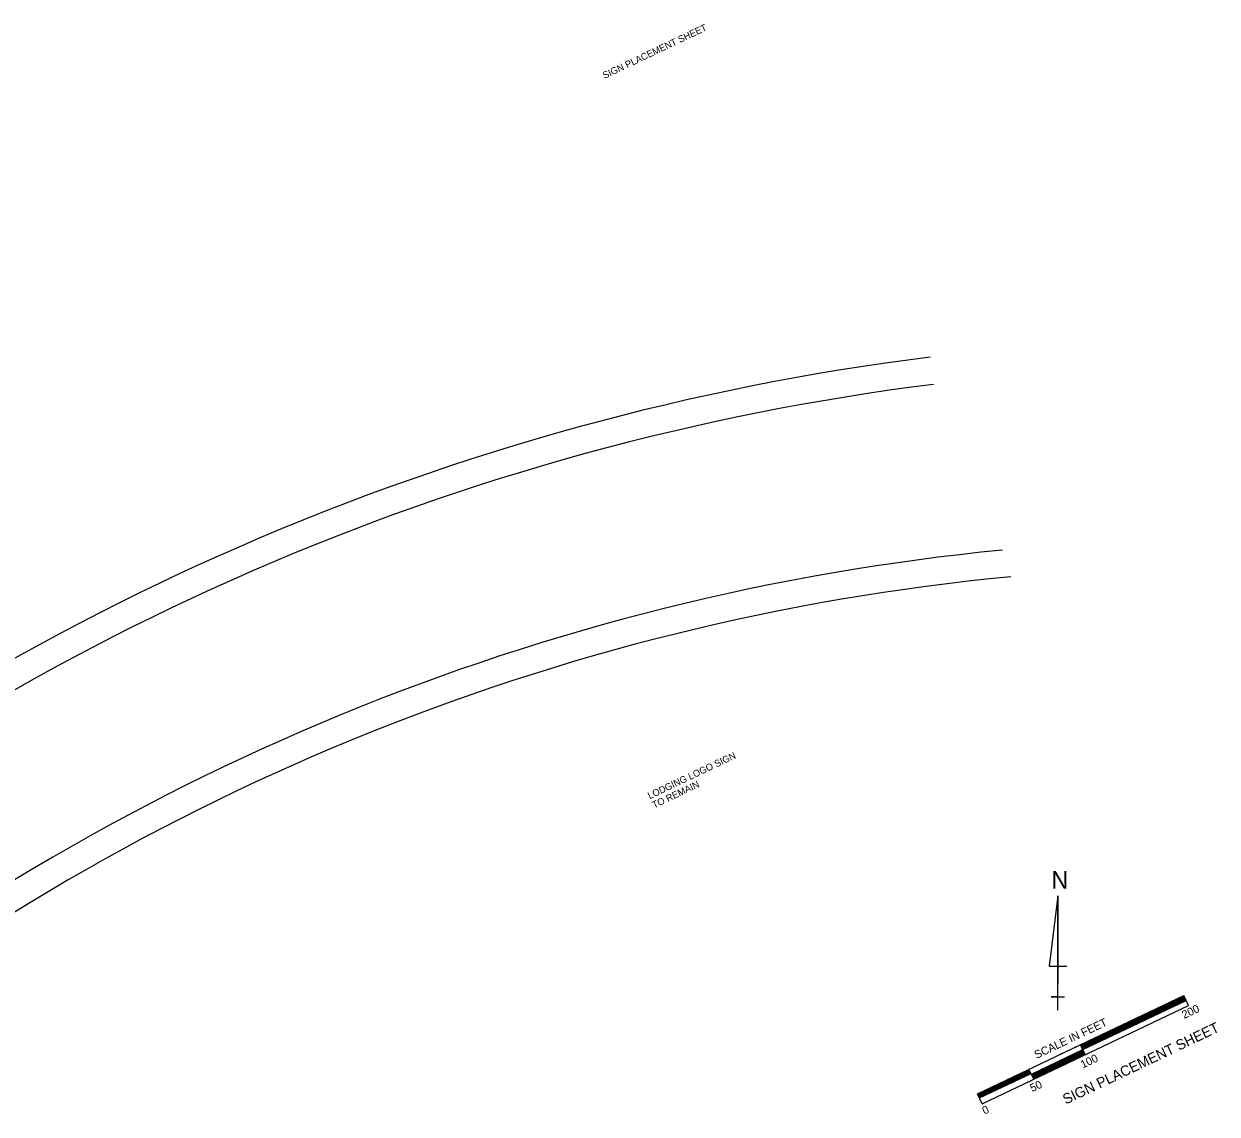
# Model space of a CAD drawing. Extents: x 601881 to 611898, y 415511 to 421131.
# Drawn here: x 602925 to 603969, y 420177 to 421131 of the extents above; entities that cross this region are included whole.
import ezdxf

# ---------------------------------------------------------------- set-up
doc = ezdxf.new("R2010")
doc.units = 0
for name, color, linetype in [('G-ANNO-TEXT', 7, 'Continuous'), ('Level 1', 7, 'Continuous'), ('Level 10', 7, 'Continuous'), ('R_Annotation', 7, 'Continuous'), ('R_Draft', 7, 'Continuous')]:
    doc.layers.add(name, color=color, linetype=linetype)

msp = doc.modelspace()

# ---------------------------------------------------------------- linework, layer by layer
at = {"layer": 'Level 1'}
for p, q in [((603829.6, 420367.5), (603821.9, 420306)), ((603829.6, 420267.5), (603829.6, 420367.5)), ((603829.6, 420367.5), (603829.6, 420290.6)), ((603821.9, 420306), (603837.3, 420306)), ((603829.6, 420267.5), (603829.6, 420290.6)), ((603829.6, 420279.1), (603823.8, 420279.1)), ((603823.8, 420279.1), (603835.3, 420279.1)), ((603829.6, 420267.5), (603829.6, 420279.1))]:
    msp.add_line(p, q, dxfattribs=at)
at = {"layer": 'Level 10'}
for p, q in [((603831.4, 420228.7), (603939.8, 420280.3)), ((603849.8, 420236.6), (603940.1, 420279.6)), ((603850.2, 420235.9), (603940.4, 420278.9)), ((603850.5, 420235.1), (603940.8, 420278.1)), ((603850.9, 420234.4), (603941.1, 420277.4)), ((603851.2, 420233.7), (603941.5, 420276.7)), ((603851.5, 420233), (603941.8, 420276)), ((603943.9, 420271.6), (603939.8, 420280.3)), ((603759.2, 420194.3), (603903.6, 420263.1)), ((603763.3, 420185.6), (603943.9, 420271.6)), ((603851.5, 420233), (603905.7, 420258.8)), ((603806.4, 420211.5), (603851.5, 420233)), ((603806.7, 420210.8), (603851.9, 420232.3)), ((603807.1, 420210), (603852.2, 420231.5)), ((603853.6, 420228.6), (603849.5, 420237.3)), ((603807.4, 420209.3), (603852.6, 420230.8)), ((603807.8, 420208.6), (603852.9, 420230.1)), ((603808.1, 420207.9), (603853.3, 420229.4)), ((603759.2, 420194.3), (603795.3, 420211.5)), ((603759.5, 420193.6), (603804.7, 420215.1)), ((603759.9, 420192.9), (603805, 420214.4)), ((603760.2, 420192.1), (603805.4, 420213.6)), ((603760.6, 420191.4), (603805.7, 420212.9)), ((603760.9, 420190.7), (603806.1, 420212.2)), ((603799.4, 420202.8), (603835.5, 420220)), ((603808.5, 420207.1), (603804.3, 420215.8)), ((603763.3, 420185.6), (603759.2, 420194.3))]:
    msp.add_line(p, q, dxfattribs=at)
at = {"layer": 'R_Draft'}
for centre, radius, start, end in [((603991.6, 418658.4), 2197.8, 97.1552, 129.8704), ((603991.6, 418658.4), 2173.8, 97.1552, 129.8704), ((603980, 418636.1), 2043.8, 95.5856, 129.2066), ((603980, 418636.1), 2019.8, 95.4433, 129.2066)]:
    msp.add_arc(centre, radius, start, end, dxfattribs=at)

# ---------------------------------------------------------------- texts
at = {"layer": 'G-ANNO-TEXT'}
for height, p in [(6, (603432.9, 421082.5)), (9, (603836.5, 420184.8))]:
    msp.add_text('SIGN PLACEMENT SHEET', height=height, rotation=25.4644, dxfattribs=at).set_placement(p)
at = {"layer": 'Level 1'}
msp.add_text('N', height=15.4, rotation=360, dxfattribs=at).set_placement((603823.9, 420373.9))
at = {"layer": 'Level 10'}
for s, height, p in [('200', 7, (603940.1, 420259.8)), ('SCALE IN FEET', 7.001, (603811, 420224.8)), ('100', 7, (603851.4, 420216.4)), ('50', 7, (603807.2, 420195.7)), ('0', 7, (603765.4, 420176))]:
    msp.add_text(s, height=height, rotation=25.4647, dxfattribs=at).set_placement(p)
at = {"layer": 'R_Annotation'}
for s, p in [('LODGING LOGO SIGN', (603472.4, 420452.1)), ('TO REMAIN', (603476.3, 420444))]:
    msp.add_text(s, height=6, rotation=25.4644, dxfattribs=at).set_placement(p)

doc.saveas('drawing.dxf')
